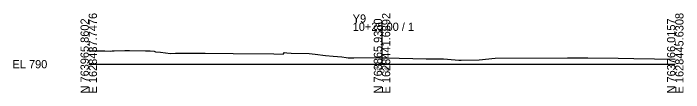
# Model space of a CAD drawing. Extents: x -26 to 203, y -10 to 6017.
# Drawn here: x -25.7 to 202.8, y 490.3 to 517.3 of the extents above; entities that cross this region are included whole.
import ezdxf

# ---------------------------------------------------------------- set-up
doc = ezdxf.new("R2010")
doc.units = 0
for name, color, linetype in [('Default', 7, 'Continuous'), ('Exist Cross Section Cell', 7, 'Continuous'), ('Exist XS Center Line Elevation Label', 7, 'Continuous'), ('Exist XS Ground Line', 7, 'Continuous')]:
    doc.layers.add(name, color=color, linetype=linetype)

msp = doc.modelspace()

# ---------------------------------------------------------------- linework, layer by layer
at = {"layer": 'Exist Cross Section Cell'}
for p, q in [((100, 500), (100, 514.17)), ((0, 500), (100, 500)), ((100, 500), (200, 500))]:
    msp.add_line(p, q, dxfattribs=at)
at = {"layer": 'Exist XS Ground Line'}
msp.add_lwpolyline([(0, 504.53), (3.21, 504.52), (3.63, 504.52), (5.53, 504.52), (7.53, 504.4), (8.02, 504.53), (8.63, 504.53), (12.35, 504.72), (13.95, 504.72), (19.34, 504.52), (20.89, 504.57), (22.32, 504.42), (22.74, 504.16), (24.41, 504.09), (27.89, 503.7), (29.55, 503.72), (39.67, 503.72), (49.25, 503.63), (63.15, 503.5), (66.29, 503.43), (66.7, 503.93), (67.59, 503.85), (68.98, 503.75), (75.2, 503.62), (77.17, 503.4), (80.68, 502.92), (83.39, 502.72), (86.27, 502.53), (87.78, 502.32), (88.46, 502.22), (90.36, 502.22), (97.89, 502.26), (100, 502.19), (101.32, 502.16), (115.01, 501.78), (117, 501.84), (117.61, 501.86), (120.53, 501.87), (120.95, 501.87), (124.89, 501.53), (126.23, 501.38), (126.94, 501.39), (133.11, 501.52), (138.61, 502.05), (163.27, 502.18), (164.22, 502.17), (170.15, 502.17), (180.52, 502.09), (185.91, 501.98), (200, 501.69)], dxfattribs=at)

# ---------------------------------------------------------------- texts
at = {"layer": 'Default'}
msp.add_text('-', height=0.0001, dxfattribs=at).set_placement((0, 500))
at = {"layer": 'Exist Cross Section Cell'}
for s, p in [('E 1628437.7476', (2.8, 490)), ('E 1628441.6892', (102.8, 490)), ('E 1628445.6308', (202.8, 490)), ('N 763965.8602', (0, 490)), ('N 763865.9380', (100, 490)), ('N 763766.0157', (200, 490))]:
    msp.add_text(s, height=2.8, rotation=90, dxfattribs=at).set_placement(p)
for s, p in [('Y9', (90, 514.17)), ('10+25.00 / 1', (90, 511.37)), ('EL 790', (-26, 498.6))]:
    msp.add_text(s, height=2.8, dxfattribs=at).set_placement(p)
at = {"layer": 'Exist XS Center Line Elevation Label'}
msp.add_text('792.20', height=1.2, dxfattribs=at).set_placement((97.4, 497.6))

doc.saveas('drawing.dxf')
